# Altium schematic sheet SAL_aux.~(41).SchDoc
size A4; PageSetup: Record=PageOptions|CenterHorizontal=True|CenterVertical=True|PrintScale=1.00|XCorrection=1.00|YCorrection=1.00|PrintKind=0|BorderSize=5000000|LeftOffset=0|BottomOffset=0|Orientation=2|PaperLength=1000|PaperWidth=1000|Scale=100|PaperSource=15|PrintQuality=1200|MediaType=1|DitherType=10|PaperKind=A4|PrintScaleMode=0
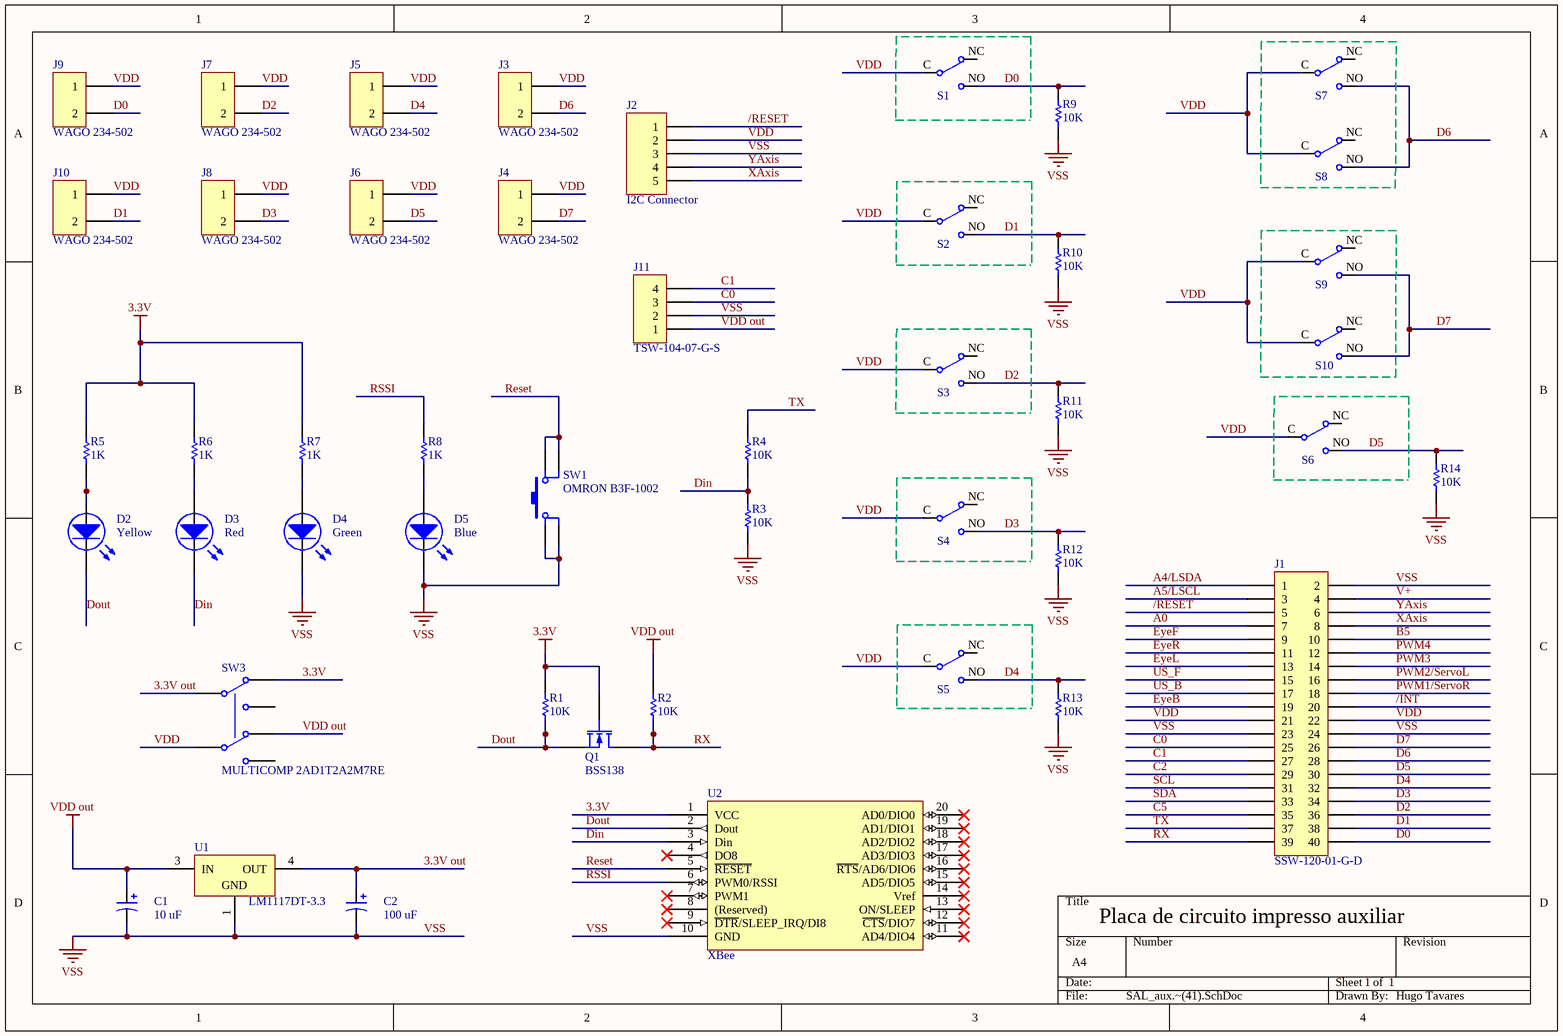
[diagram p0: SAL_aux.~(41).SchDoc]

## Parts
C1  10 uF  [PANASONIC ECA1HAM100X]
C2  100 uF  [PANASONIC ECA1HAM101X]
D2  Yellow  [VISHAY TLLR4401]
D3  Red  [VISHAY TLLR4401]
D4  Green  [VISHAY TLLR4401]
D5  Blue  [VISHAY TLLR4401]
J1  SSW-120-01-G-D  [SAMTEC SSW-120-1-G-D]
J2  I2C Connector  [TYCO 640456-5]
J3  WAGO 234-502  [WAGO 234-502]
J4  WAGO 234-502  [WAGO 234-502]
J5  WAGO 234-502  [WAGO 234-502]
J6  WAGO 234-502  [WAGO 234-502]
J7  WAGO 234-502  [WAGO 234-502]
J8  WAGO 234-502  [WAGO 234-502]
J9  WAGO 234-502  [WAGO 234-502]
J10  WAGO 234-502  [WAGO 234-502]
J11  TSW-104-07-G-S  [SAMTEC TSW-104-XX-X-S]
Q1  BSS138  [SOT23]
R1  10K  [Resistência]
R2  10K  [Resistência]
R3  10K  [Resistência]
R4  10K  [Resistência]
R5  1K  [Resistência]
R6  1K  [Resistência]
R7  1K  [Resistência]
R8  1K  [Resistência]
R9  10K  [Resistência]
R10  10K  [Resistência]
R11  10K  [Resistência]
R12  10K  [Resistência]
R13  10K  [Resistência]
R14  10K  [Resistência]
S1  CHERRY switch  (value not drawn)
S2  CHERRY switch  (value not drawn)
S3  CHERRY switch  (value not drawn)
S4  CHERRY switch  (value not drawn)
S5  CHERRY switch  (value not drawn)
S6  CHERRY switch  (value not drawn)
S7  CHERRY switch  (value not drawn)
S8  CHERRY switch  (value not drawn)
S9  CHERRY switch  (value not drawn)
S10  CHERRY switch  (value not drawn)
SW1  OMRON B3F-1002  [OMRON B3F-1002]
SW3  MULTICOMP 2AD1T2A2M7RE  [MULTICOMP 2AD1T2A2M7RE]
U1  LM1117DT-3.3  [TD03B_N]
U2  XBee  [XBee]

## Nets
3.3V: Q1.3(G) R1.2 R5.1 R6.1 R7.1 SW3.6(NC2) U2.1(VCC)
VDD out: C1.2 J11.1 R2.2 SW3.3(NC1) U1.3(IN)
VSS: C1.1 C2.1 D4.2(K) D5.2(K) J1.2 J1.23 J1.24 J2.3 J11.2 R3.1 R9.1 R10.1 R11.1 R12.1 R13.1 R14.1 SW1.3 SW1.4 SW3.GND U1.1(GND) U2.10(GND)
3.3V out: C2.2 SW3.5(COMMON2) U1.4(OUT)
/INT: J1.20
/RESET: J1.5 J2.1
A0: J1.7
A4/LSDA: J1.1
A5/LSCL: J1.3
B5: J1.10
C0: J1.25 J11.3
C1: J1.27 J11.4
C2: J1.29
C5: J1.35
D0: J1.40 J9.3(2) R9.2 S1.NO
D1: J1.38 J10.3(2) R10.2 S2.NO
D2: J1.36 J7.3(2) R11.2 S3.NO
D3: J1.34 J8.3(2) R12.2 S4.NO
D4: J1.32 J5.3(2) R13.2 S5.NO
D5: J1.30 J6.3(2) R14.2 S6.NO
D6: J1.28 J3.3(2) S7.NO S8.NO
D7: J1.26 J4.3(2) S9.NO S10.NO
Din: D3.2(K) R3.2 R4.1 U2.3(Din)
Dout: D2.2(K) Q1.2(S) R1.1 U2.2(Dout)
EyeB: J1.19
EyeF: J1.9
EyeL: J1.13
EyeR: J1.11
PWM1/ServoR: J1.18
PWM2/ServoL: J1.16
PWM3: J1.14
PWM4: J1.12
Reset: SW1.1 SW1.2 U2.5(~{RESET})
RSSI: R8.1 U2.6(PWM0/RSSI)
RX: J1.39 Q1.1(D) R2.1
SCL: J1.31
SDA: J1.33
TX: J1.37 R4.2
US_B: J1.17
US_F: J1.15
V+: J1.4
VDD: J1.21 J1.22 J2.2 J3.1 J4.1 J5.1 J6.1 J7.1 J8.1 J9.1 J10.1 S1.C S2.C S3.C S4.C S5.C S6.C S7.C S8.C S9.C S10.C SW3.2(COMMON1)
XAxis: J1.8 J2.5
YAxis: J1.6 J2.4
NetD2_1: D2.1(A) R5.2
NetD3_1: D3.1(A) R6.2
NetD4_1: D4.1(A) R7.2
NetD5_1: D5.1(A) R8.2

Not connected (* = marked no-connect by the designer): J3 2 4; J4 2 4; J5 2 4; J6 2 4; J7 2 4; J8 2 4; J9 2 4; J10 2 4; S1 NC(4); S2 NC(4); S3 NC(4); S4 NC(4); S5 NC(4); S6 NC(4); S7 NC(4); S8 NC(4); S9 NC(4); S10 NC(4); SW3 1(NO1) 4(NO2); U2 4(DO8)* 7(PWM1)* 8((Reserved))* 9(~{DTR}/SLEEP_IRQ/DI8)* 11(AD4/DIO4)* 12(~{CTS}/DIO7)* 13(ON/SLEEP)* 14(Vref)* 15(AD5/DIO5)* 16(~{RTS}/AD6/DIO6)* 17(AD3/DIO3)* 18(AD2/DIO2)* 19(AD1/DIO1)* 20(AD0/DIO0)*

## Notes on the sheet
- Placa de circuito impresso auxiliar
- 1      1
- Hugo Tavares

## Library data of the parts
C1 = PANASONIC ECA1HAM100X
C2 = PANASONIC ECA1HAM101X
D2-D5 = VISHAY TLLG4401: Green LED PCB 3mm
J1 = SAMTEC SSW-120-01-G-D
J2 = TYCO 640456-5
J11 = SAMTEC TSW-104-07-G-S: 4 pin 2.54mm pitch header
Q1 = BSS138: N-Channel Enhancement Mode Vertical DMOS FET
R1-R14 = Resistência
SW1 = OMRON B3F-1002: 6.0mm Tact Switch
U1 = LM1117DT-3.3: 800mA Low-Dropout Linear Regulator; Manufacturer: National Semiconductor; CompType: LDO IC; PackageTopMarking: NSUZXYTT*LM1117*DT-3.3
